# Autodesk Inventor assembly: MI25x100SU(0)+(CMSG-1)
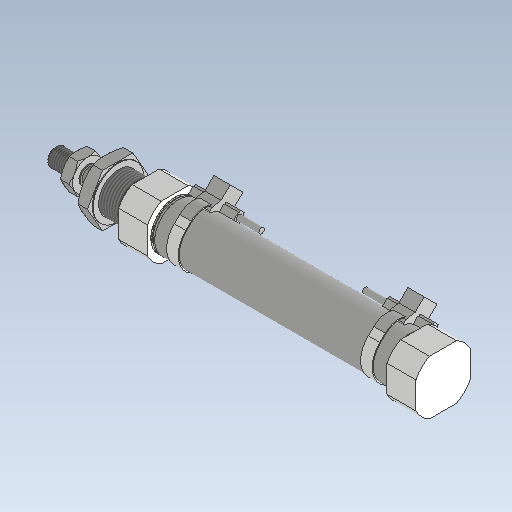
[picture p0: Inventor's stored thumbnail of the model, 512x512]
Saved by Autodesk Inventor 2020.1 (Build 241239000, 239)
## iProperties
Company: CADENAS
Created: 2020-04
Part Number: MI25x100SU(0)+(CMSG-1)
Description: Mini Cylinder - AirTAC
Document SubType Name: Assembly
Designer: Safarabadi
Sending System: PARTsolutions
Author: License CC BY-ND 4.0
Revision Number: NONE
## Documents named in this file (6)
- C:\Users\Safarabadi\Desktop\00-GrabCAD\00-Mask\MPB (75) - Face mask ear loop welding machine - (3D & 2D)\MPB-14-00-00-00 (V2)\MI25x100SU(0)+(CMSG-1)\MI25x100SU(0)+(CMSG-1).iam
- C:\Users\Safarabadi\Desktop\00-GrabCAD\00-Mask\MPB (75) - Face mask ear loop welding machine - (3D & 2D)\MPB-14-00-00-00 (V2)\MI25x100SU(0)+(CMSG-1)\_MI 25x100-S-U_c.ipt
- C:\Users\Safarabadi\Desktop\00-GrabCAD\00-Mask\MPB (75) - Face mask ear loop welding machine - (3D & 2D)\MPB-14-00-00-00 (V2)\MI25x100SU(0)+(CMSG-1)\_MI 25x100-S-U_r.ipt
- C:\Users\Safarabadi\Desktop\00-GrabCAD\00-Mask\MPB (75) - Face mask ear loop welding machine - (3D & 2D)\MPB-14-00-00-00 (V2)\MI25x100SU(0)+(CMSG-1)\_MI25-M10x1.5 - Nut.ipt
- C:\Users\Safarabadi\Desktop\00-GrabCAD\00-Mask\MPB (75) - Face mask ear loop welding machine - (3D & 2D)\MPB-14-00-00-00 (V2)\MI25x100SU(0)+(CMSG-1)\_MI25-M22x1.5 - Nut.ipt
- C:\Users\Safarabadi\Desktop\00-GrabCAD\00-Mask\MPB (75) - Face mask ear loop welding machine - (3D & 2D)\MPB-14-00-00-00 (V2)\MI25x100SU(0)+(CMSG-1)\_CS1-M-S25-P.ipt
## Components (6 placed, 6 different names)
1. NAUO1 — Mate:1, Mate:2, Flush:1, Flush:2, Insert:1, Mate:5
2. NAUO2 — Mate:1, Mate:2, Flush:1, Flush:2, Insert:2
3. NAUO3 — Insert:2
4. NAUO4 — Insert:1
5. NAUO5 — Mate:3, Flush:5
6. _CS1-M-S25-P:2 — Mate:3, Flush:5, Mate:5
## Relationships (9: Mate 4, Flush 3, Insert 2)
- Mate:1: NAUO1 ↔ NAUO2
- Mate:2: NAUO1 ↔ NAUO2
- Flush:1: NAUO1 ↔ NAUO2
- Flush:2: NAUO1 ↔ NAUO2
- Insert:1: NAUO1 ↔ NAUO4
- Insert:2: NAUO2 ↔ NAUO3
- Mate:3: NAUO5 ↔ _CS1-M-S25-P:2
- Flush:5: NAUO5 ↔ _CS1-M-S25-P:2
- Mate:5: NAUO1 ↔ _CS1-M-S25-P:2
